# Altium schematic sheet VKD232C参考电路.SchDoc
size A4
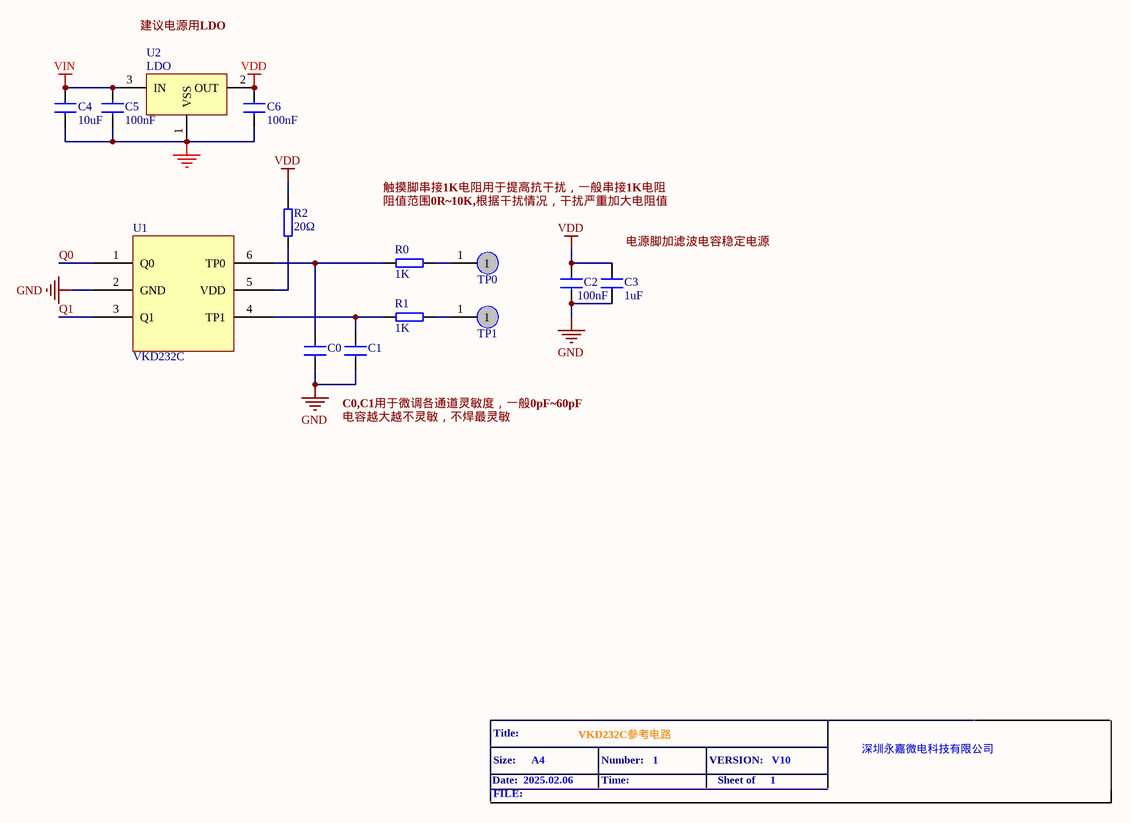
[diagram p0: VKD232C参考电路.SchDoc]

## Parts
C0  10uF  [0603-C]  (value not drawn)
C1  10uF  [0603-C]  (value not drawn)
C2  100nF  [0603-C]
C3  value 1uF  [0603-C]  (hidden comment: 10uF)
C4  10uF  [0805-C]
C5  100nF  [0805-C]
C6  100nF  [0805-C]
R0  1K  [0603-R]
R1  1K  [0603-R]
R2  20Ω  [0603-R]
TP0  TPAD  [TP-PAD0]  (value not drawn)
TP1  TPAD  [TP-PAD0]  (value not drawn)
U1  VKD232C
U2  LDO  [SOT-23]

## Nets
GND: C0.1 C1.2 C2.2 C3.2 C4.2 C5.2 C6.2 U1.2(GND) U2.1(VSS)
VDD: C2.1 C3.1 C6.1 R2.1 U2.2(OUT)
VIN: C4.1 C5.1 U2.3(IN)
Q0: U1.1(Q0)
Q1: U1.3(Q1)
NetC0_2: C0.2 R0.2 U1.6(TP0)
NetC1_1: C1.1 R1.2 U1.4(TP1)
NetR0_1: R0.1 TP0.1
NetR1_1: R1.1 TP1.1
NetR2_2: R2.2 U1.5(VDD)

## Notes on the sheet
- 建议电源用LDO
- 触摸脚串接1K电阻用于提高抗干扰，一般串接1K电阻
- 阻值范围0R
  0K,根据干扰情况，干扰严重加大电阻值
- (near C3) 电源脚加滤波电容稳定电源
- C0,C1用于微调各通道灵敏度，一般0pF~60pF
- 电容越大越不灵敏，不焊最灵敏
- Date:
- Title:
- Size:
- 2025.02.06
- A4
- VKD232C参考电路
- Number:
- Time:
- 1
- VERSION:
- Sheet of
- V10
- 深圳永嘉微电科技有限公司
- FILE:

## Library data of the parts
C0 C2-C6 = CAP: Capacitor
C1 = CAP: Capacitor; Value: N
R0-R2 = RES: Resistor
TP0 TP1 = TPAD: TESTING
U2 = V6206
